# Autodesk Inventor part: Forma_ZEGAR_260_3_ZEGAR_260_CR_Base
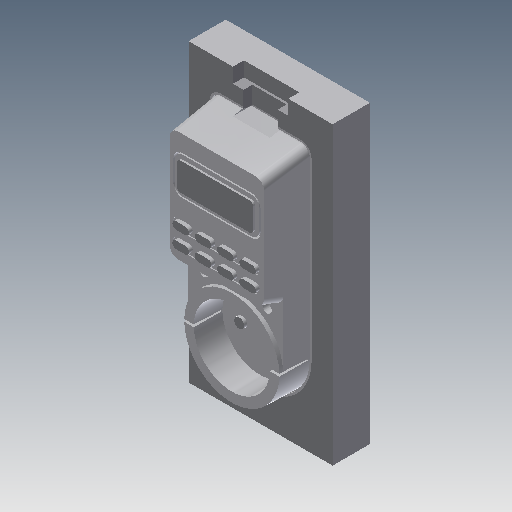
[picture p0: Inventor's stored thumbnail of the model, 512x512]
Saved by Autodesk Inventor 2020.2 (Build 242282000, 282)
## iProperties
Created: 2015-01
Part Number: Forma_ZEGAR_260_3_ZEGAR_260_CR_Base
Material: Ogólny
Document SubType Name: Modeling
Designer: F.Stasiak
Density: 1 g/cm^3
Appearance: Domyślna
Catalog Web Link: www.expertbooks.pl
Manager: www.cadconsulting.pl
Company: Fabian Stasiak CAD Consulting
Author: F.Stasiak
Subject: Zbiór ćwiczeń. Autodesk Inventor 2020. Kurs Professional
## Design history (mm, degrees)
node "Forma_ZEGAR_260_3_ZEGAR_260_MP"
feature "Rzeźbienie1"
feature "Bryła3::Forma_ZEGAR_260_3_ZEGAR_260_MP"
tag "Bryła wyprowadzona1"
node "Bryła1"
feature "Forma_ZEGAR_260_3_ZEGAR_260_MP_Bodies"
feature "Powierzchnia1"
body "Srf1"
